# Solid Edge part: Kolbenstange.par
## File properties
Username: bmolnar
Dokumentum tartalom típus: 0
Author: bmolnar
Last saved by: bmolnar
Revision: 84
Sűrűség: 0,000 kg/m^3
Pontosság: 0,990
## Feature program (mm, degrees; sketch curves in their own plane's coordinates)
base feature "unnamed BaseFeature 1"
sketch for "unnamed Protrusion 1" plane through (23.4, 0, 0) normal (1, 0, 0) x-axis (0, 1, 0)
  circle centre (0, 0) radius 10
extrude "unnamed Protrusion 1" add finite 12.5 along +normal
sketch for "Kihúzás_2" #1 plane through (23.4, 0, 0) normal (1, 0, 0) x-axis (0, 1, 0)
  circle centre (0, 0) radius 10
sketch for "Kihúzás_2" #2 plane through (23.4, 0, 0) normal (1, 0, 0) x-axis (0, 1, 0)
  circle centre (0, 0) radius 5
extrude "Kihúzás_2" add finite 16.4 along -normal
sketch for "Furat_1" plane through (-49, 0, 0.0012) normal (-1, 0, 0) x-axis (0, -1, 0)
  hole centre (0, -0.0012) bore radius 2.067
hole "Furat_1" nominal diameter 5 finite  VBottomAngle = 118 deg; ThreadDepth = 10 mm
chamfer "Letörés_1" setback 0.3  SetBackValue2 = 45 deg
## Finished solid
Body 1: solid body, 18 faces, 24 edges, 8 vertices.
  Faces by surface: plane 8, cylinder 5, cone 3, torus 2
  Edges by curve: circle 14, line 6, curve on surface 2, ellipse 2
Bounding box of the edges (mm; curved faces can reach further): 86.900 x 20.000 x 20.000, from (-51, -10, -10) to (35.9, 10, 10).
Cylindrical faces by radius (mm): R2.067 x2, R2.625 x1, R5 x1, R10 x1
Conical faces (half-angle, radius in mm at the cone's reference point): 45 deg R2.367 x1, 45 deg R2.725 x1, 59 deg R2.067 x1
Toroidal faces (ring radius, tube radius in mm): R2.425 r0.2 x1, R3.7 r1.3 x1
Planar faces by outward normal: +x 1, +z 1, -x 3, -z 1, oblique 2
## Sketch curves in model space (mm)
circle centre (23.4, 0, 0) radius 10
circle centre (23.4, 0, 0) radius 5
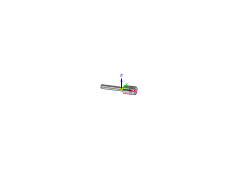
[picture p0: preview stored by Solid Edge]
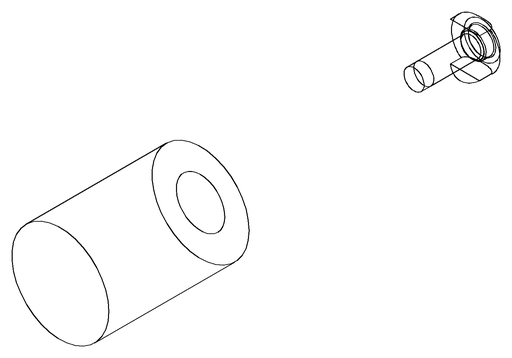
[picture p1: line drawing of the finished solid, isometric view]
